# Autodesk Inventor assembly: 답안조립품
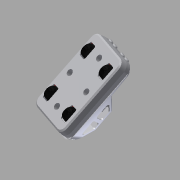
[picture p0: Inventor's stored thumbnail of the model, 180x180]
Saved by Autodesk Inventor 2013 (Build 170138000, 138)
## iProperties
Created: 2015-05
Part Number: 답안조립품
Document SubType Name: Assembly
Designer: WINDOWS7
Author: WINDOWS7
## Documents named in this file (7)
- C:\Users\WINDOWS7\Desktop\450508V1040\답안조립품.iam
- C:\Users\WINDOWS7\Desktop\450508V1040\본체.ipt
- C:\Users\WINDOWS7\Desktop\450508V1040\커버.ipt
- C:\Users\WINDOWS7\Desktop\450508V1040\바퀴고정부.ipt
- C:\Users\WINDOWS7\Desktop\450508V1040\M2x4.ipt
- C:\Users\WINDOWS7\Desktop\450508V1040\바퀴.ipt
- C:\Users\WINDOWS7\Desktop\450508V1040\M4x10.ipt
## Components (20 placed, 2 different names)
1. M2x4:1
2. M2x4:2
3. M2x4:3
4. M2x4:4
5. M2x4:5
6. M2x4:6
7. M2x4:7
8. M2x4:8
9. M2x4:9
10. M2x4:10
11. M2x4:11
12. M2x4:12
13. M2x4:13
14. M2x4:14
15. M2x4:15
16. M2x4:16
17. M4x10:1
18. M4x10:2
19. M4x10:3
20. M4x10:4
